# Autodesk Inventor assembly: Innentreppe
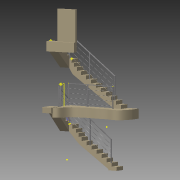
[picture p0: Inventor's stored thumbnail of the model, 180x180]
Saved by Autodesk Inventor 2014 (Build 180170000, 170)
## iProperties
Created: 2013-09
Part Number: Innentreppe
Document SubType Name: Assembly
Designer: Stefan Tammegger
Author: Stefan Tammegger
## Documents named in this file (6)
- Q:\PROJEKTE\INVENTOR\Füchsl Christian\Innentreppe\Innentreppe.iam
- Q:\PROJEKTE\INVENTOR\Füchsl Christian\Innentreppe\Bestand.ipt
- Q:\PROJEKTE\INVENTOR\Füchsl Christian\Innentreppe\Lauf 1.ipt
- C:\Program Files (x86)\Autodesk\Content Service\de-DE\DIN 1587\DIN 1587 - M10 x 1,5.ipt
- Q:\PROJEKTE\INVENTOR\Füchsl Christian\Innentreppe\Lauf 3.ipt
- Q:\PROJEKTE\INVENTOR\Füchsl Christian\Innentreppe\Lauf 2.ipt
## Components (25 placed, 5 different names)
1. Bestand:1 — Fluchtend:1, Fluchtend:2, Fluchtend:3, Fluchtend:4, Fluchtend:5, Fluchtend:6, Fluchtend:8, Fluchtend:9, Fluchtend:10, Passend:3, Passend:4, Passend:5, Fluchtend:11, Passend:6, Passend:7, Passend:8, Fluchtend:12, Passend:11, Fluchtend:13, Fluchtend:15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
2. Lauf 1:1 — Fluchtend:1, Fluchtend:2, Fluchtend:3, Fluchtend:4, Fluchtend:5, Fluchtend:6, Fluchtend:8, Fluchtend:9, Fluchtend:10, Passend:3, Passend:4, Passend:5, Fluchtend:28, Fluchtend:29, Fluchtend:30
3. DIN 1587 M10:1
4. DIN 1587 M10:2
5. DIN 1587 M10:3
6. DIN 1587 M10:4
7. DIN 1587 M10:5
8. Lauf 3:1 — Fluchtend:11, Passend:6, Passend:7, Passend:8, Fluchtend:12, Passend:11, Fluchtend:13, Fluchtend:15, Fluchtend:16, Fluchtend:17, Passend:12, Passend:13, Passend:15, Fluchtend:18, Passend:16, Fluchtend:19, Fluchtend:20, Fluchtend:21, Passend:17, Passend:18
9. DIN 1587 M10:8
10. DIN 1587 M10:9
11. DIN 1587 M10:10
12. DIN 1587 M10:11
13. DIN 1587 M10:12
14. DIN 1587 M10:13
15. Lauf 2:1 — Fluchtend:22, Fluchtend:23, Fluchtend:24, Fluchtend:25, Fluchtend:26, Fluchtend:27
16. DIN 1587 M10:14
17. DIN 1587 M10:15
18. DIN 1587 M10:16
19. DIN 1587 M10:17
20. DIN 1587 M10:18
21. DIN 1587 M10:19
22. DIN 1587 M10:20
23. DIN 1587 M10:21
24. DIN 1587 M10:22
25. DIN 1587 M10:23
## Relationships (41: Flush 28, Mate 13)
- Fluchtend:1 [Flush]: Bestand:1 ↔ Lauf 1:1
- Fluchtend:2 [Flush]: Bestand:1 ↔ Lauf 1:1
- Fluchtend:3 [Flush]: Bestand:1 ↔ Lauf 1:1
- Fluchtend:4 [Flush]: Bestand:1 ↔ Lauf 1:1
- Fluchtend:5 [Flush]: Bestand:1 ↔ Lauf 1:1
- Fluchtend:6 [Flush]: Bestand:1 ↔ Lauf 1:1
- Fluchtend:8 [Flush]: Bestand:1 ↔ Lauf 1:1
- Fluchtend:9 [Flush]: Bestand:1 ↔ Lauf 1:1
- Fluchtend:10 [Flush]: Bestand:1 ↔ Lauf 1:1
- Passend:3 [Mate]: Bestand:1 ↔ Lauf 1:1
- Passend:4 [Mate]: Bestand:1 ↔ Lauf 1:1
- Passend:5 [Mate]: Bestand:1 ↔ Lauf 1:1
- Fluchtend:11 [Flush]: Bestand:1 ↔ Lauf 3:1
- Passend:6 [Mate]: Bestand:1 ↔ Lauf 3:1
- Passend:7 [Mate]: Bestand:1 ↔ Lauf 3:1
- Passend:8 [Mate]: Bestand:1 ↔ Lauf 3:1
- Fluchtend:12 [Flush]: Bestand:1 ↔ Lauf 3:1
- Passend:11 [Mate]: Bestand:1 ↔ Lauf 3:1
- Fluchtend:13 [Flush]: Bestand:1 ↔ Lauf 3:1
- Fluchtend:15 [Flush]: Bestand:1 ↔ Lauf 3:1
- Fluchtend:16 [Flush]: Bestand:1 ↔ Lauf 3:1
- Fluchtend:17 [Flush]: Bestand:1 ↔ Lauf 3:1
- Passend:12 [Mate]: Bestand:1 ↔ Lauf 3:1
- Passend:13 [Mate]: Bestand:1 ↔ Lauf 3:1
- Passend:15 [Mate]: Bestand:1 ↔ Lauf 3:1
- Fluchtend:18 [Flush]: Bestand:1 ↔ Lauf 3:1
- Passend:16 [Mate]: Bestand:1 ↔ Lauf 3:1
- Fluchtend:19 [Flush]: Bestand:1 ↔ Lauf 3:1
- Fluchtend:20 [Flush]: Bestand:1 ↔ Lauf 3:1
- Fluchtend:21 [Flush]: Bestand:1 ↔ Lauf 3:1
- Passend:17 [Mate]: Bestand:1 ↔ Lauf 3:1
- Passend:18 [Mate]: Bestand:1 ↔ Lauf 3:1
- Fluchtend:22 [Flush]: Bestand:1 ↔ Lauf 2:1
- Fluchtend:23 [Flush]: Bestand:1 ↔ Lauf 2:1
- Fluchtend:24 [Flush]: Bestand:1 ↔ Lauf 2:1
- Fluchtend:25 [Flush]: Bestand:1 ↔ Lauf 2:1
- Fluchtend:26 [Flush]: Bestand:1 ↔ Lauf 2:1
- Fluchtend:27 [Flush]: Bestand:1 ↔ Lauf 2:1
- Fluchtend:28 [Flush]: Bestand:1 ↔ Lauf 1:1
- Fluchtend:29 [Flush]: Bestand:1 ↔ Lauf 1:1
- Fluchtend:30 [Flush]: Bestand:1 ↔ Lauf 1:1
